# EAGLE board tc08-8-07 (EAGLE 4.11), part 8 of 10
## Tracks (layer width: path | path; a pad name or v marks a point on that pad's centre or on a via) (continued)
N$155  (via drill 0.61) (continued)
  Route15 0.254: v196.89,121.59 v192.44,126.03 | v211.17,122.22 v214.03,122.22 | v223.24,119.69 223.56,119.69 v230.22,113.02 | v233.4,112.38 v236.26,109.52
  Bottom 0.254: v196.89,121.59 197.2,121.91 210.86,121.91 v211.17,122.22 | v214.03,122.22 214.35,121.91 214.98,121.91 217.52,119.37 222.92,119.37 v223.24,119.69 | v230.22,113.02 230.86,112.38 v233.4,112.38 | v236.26,109.52 236.57,109.84 238.48,109.84 242.92,114.29 C10.L1
N$161  (via drill 0.61)
  Top 0.254: v251.5,257.48 251.18,257.16 251.18,250.81 254.35,247.64 254.35,243.83 255.31,242.87 255.31,238.75 A09.P2
  Bottom 0.254: v251.5,257.48 250.54,258.43 245.15,258.43 244.51,259.07 234.99,259.07 234.03,260.02 A11.F1
N$162  (via drill 0.61)
  Top 0.254: A12.D1 220.38,267.32 220.38,272.4 A12.B1 | v236.26,261.93 236.26,257.8 A11.H1
  Bottom 0.254: v236.26,261.93 232.76,265.42 224.83,265.42 223.87,266.37 221.33,266.37 A12.D1
N$185  (via drill 0.61)
  Top 0.254: v215.62,141.59 215.94,141.91 v215.94,147.94 | v220.06,147.94 221.02,148.89 221.02,150.8 221.97,151.75 221.97,156.52 v221.65,156.83 | v228.32,155.56 228.64,155.24 228.64,140.64 v228.95,140.32
  Route15 0.254: v201.97,141.91 200.38,140.32 200.38,138.74 198.79,137.15 C14.C1 | v228.95,140.32 229.59,140.32 v239.43,130.48
  Bottom 0.254: v201.97,141.91 202.28,141.59 204.19,141.59 204.51,141.27 205.78,141.27 206.09,141.59 v215.62,141.59 | v215.94,147.94 v220.06,147.94 | v221.65,156.83 225.46,156.83 226.73,155.56 v228.32,155.56 | v239.43,130.48 241.34,130.48 242.29,131.43 246.1,131.43 247.05,130.48 248.64,130.48 C10.E1
N$193  (via drill 0.61)
  Top 0.254: v197.2,114.29 196.25,115.24 196.25,119.37 195.62,120 C14.J1
  Route15 0.254: v205.14,106.35 v197.2,114.29 | v217.84,107.3 218.16,107.3 220.38,105.08 221.65,105.08 226.41,100.32 230.22,100.32 v232.45,98.1
  Bottom 0.254: v205.14,106.35 205.46,106.67 217.21,106.67 v217.84,107.3 | v232.45,98.1 234.03,96.51 241.34,96.51 241.97,95.87 242.61,95.87 244.83,98.1 248.64,98.1 C10.S1
PAR  (via drill 0.61)
  Top 0.254: v45.76,247.96 47.34,246.37 47.34,241.29 48.3,240.33 48.3,239.7 47.98,239.38 47.98,234.3 53.69,228.59 53.69,224.78 55.28,224.78 55.92,225.41 55.92,227.95 A25.T1 | v43.22,249.86 41.63,251.45 41.63,254.62 40.99,255.26 40.99,261.61 v42.58,263.19 | v45.12,265.74 44.8,266.05 44.8,282.56 v54.33,292.09 | v291.82,295.9 298.49,295.9 298.49,267.96 298.8,267.64 298.8,262.88 299.12,262.56 299.12,258.11 298.8,257.8 298.8,251.45 298.49,251.13 298.49,249.86 v298.8,249.54
  Route2 0.254: v293.72,247 293.72,246.68 276.58,229.54 276.58,227.64 274.99,226.05 A08.U1
  Bottom 0.254: v45.76,247.96 43.85,249.86 v43.22,249.86 | v45.12,265.74 v42.58,263.19 | v54.33,292.09 54.96,291.45 56.23,291.45 57.19,290.5 62.27,290.5 62.9,289.86 81.95,289.86 83.22,291.13 97.19,291.13 97.83,290.5 130.53,290.5 132.12,292.09 144.18,292.09 144.5,291.77 181.33,291.77 182.6,293.04 202.92,293.04 203.24,292.72 206.41,292.72 206.73,293.04 209.27,293.04 211.17,294.94 230.22,294.94 231.18,293.99 234.67,293.99 235.3,294.63 267.69,294.63 268.96,295.9 v291.82,295.9 | v298.8,249.54 298.17,248.91 295.63,248.91 v293.72,247
PAR\  (via drill 0.61)
  Top 0.254: v223.56,271.45 222.6,270.5 222.6,265.1 223.56,264.15 A12.E1 | v274.36,271.45 273.4,270.5 273.4,236.52 274.67,235.26 A08.S1 | v325.16,179.06 325.16,175.25 B04.M1 | v288.96,205.73 289.28,206.05 289.28,220.33 v288.33,221.29 | v274.36,222.24 273.09,223.51 273.09,228.9 271.5,230.49 v271.18,230.49
  Route15 0.254: v325.16,179.06 324.84,179.06 315.95,187.95 315.31,187.95 312.14,191.12 312.14,192.08 v302.93,201.28
  Bottom 0.254: v223.56,271.45 226.41,274.31 253.72,274.31 254.04,273.99 257.85,273.99 258.16,274.31 266.42,274.31 269.59,271.13 274.04,271.13 v274.36,271.45 | v302.93,201.28 301.03,203.19 298.8,203.19 297.53,204.46 290.23,204.46 v288.96,205.73 | v288.33,221.29 288.01,220.97 275.63,220.97 v274.36,222.24 | v271.18,230.49 272.13,231.45 274.04,231.45 A08.S1
PC+ES  (via drill 0.61)
  Top 0.254: v229.27,268.28 228.95,267.96 228.95,258.75 229.91,257.8 A11.H2
  Route15 0.254: v229.27,268.28 228.32,269.23 224.83,269.23 224.51,269.55 A12.C1
PC+ES\
  Top 0.254: B11.R2 226.73,165.72 225.78,166.68 225.78,203.82 227.05,205.09 227.05,220.33 225.78,221.6 225.78,252.4 226.73,253.35 A11.J2
PWR_CLR\  (via drill 0.61)
  Top 0.254: v222.6,246.05 222.6,255.26 221.97,255.89 221.97,271.13 223.87,273.04 A12.A1 | A10.H2 242.92,253.99 244.19,252.72 244.19,247.64 242.92,246.37 A10.M2 | v230.22,96.83 C11.U2 | v234.03,73.33 234.35,73.65 234.35,87.94 234.67,88.25 234.67,90.79 v233.72,91.74 | v314.36,147.31 314.36,140.96 314.04,140.64 314.04,119.05 313.09,118.1 C05.K1 | v268.32,147.31 B08.U2 | v270.23,90.79 270.23,94.6 269.91,94.92 269.91,95.55 270.23,95.87 270.23,110.8 271.82,112.38 271.82,112.7 272.45,113.33 273.72,113.33 273.72,112.07 273.4,111.75 273.4,108.89 v274.04,108.25 | v81.63,242.87 82.27,242.87 83.54,244.14 A23.M1 | v73.06,241.61 70.2,238.75 70.2,229.22 v70.52,228.9 | v28.61,227.64 28.29,227.32 v28.29,146.36 | v89.57,112.7 89.25,112.38 89.25,69.84 91.79,67.3 v91.79,62.22 | v170.22,59.36 v172.44,57.14 | v189.58,60.63 190.54,61.58 190.54,66.98 193.39,69.84 193.39,72.38 194.03,73.01 194.03,87.3 193.08,88.25 v193.08,89.21 | v194.98,91.74 194.66,92.06 194.66,93.97 193.71,94.92 193.71,97.14 194.98,98.41 194.98,100.95 C14.R1
  Route2 0.254: v193.08,89.21 193.08,89.84 v194.98,91.74
  Route15 0.254: v256.26,90.47 v258.16,92.38
  Bottom 0.254: 222.6,245.73 237.84,245.73 239.11,244.46 A10.M2 | 222.6,245.73 168.95,245.73 168.63,246.05 164.18,246.05 163.87,245.73 105.45,245.73 105.13,246.05 90.21,246.05 89.89,245.73 85.76,245.73 84.81,244.78 A23.M1 | 222.6,245.73 v222.6,246.05 | v230.22,96.83 231.49,96.83 231.49,99.05 230.86,99.68 197.52,99.68 195.93,101.27 C14.R1 | v234.03,73.33 235.94,73.33 D11.A1 | C11.U2 230.86,91.74 v233.72,91.74 234.03,91.43 235.3,91.43 235.94,90.79 246.73,90.79 247.05,91.11 248.32,91.11 248.64,90.79 253.08,90.79 253.4,91.11 254.67,91.11 255.31,90.47 v256.26,90.47 | 307.69,115.56 309.28,117.14 312.14,117.14 C05.K1 | 307.69,115.56 298.17,106.03 295.31,106.03 294.36,105.08 C06.P2 | v268.32,147.31 268.64,146.99 314.04,146.99 v314.36,147.31 | v258.16,92.38 259.12,93.33 262.61,93.33 263.56,92.38 263.56,91.43 267.05,91.43 267.69,90.79 v270.23,90.79 | v274.04,108.25 274.36,108.57 276.58,108.57 283.56,115.56 307.69,115.56 | v81.63,242.87 74.33,242.87 v73.06,241.61 | v70.52,228.9 68.93,227.32 40.68,227.32 40.36,227.64 37.5,227.64 37.18,227.32 28.93,227.32 v28.61,227.64 | v28.29,146.36 28.29,140.96 37.5,140.96 65.76,112.7 v89.57,112.7 | v91.79,62.22 95.6,58.41 145.13,58.41 145.77,59.04 169.9,59.04 v170.22,59.36 | v172.44,57.14 174.34,59.04 188,59.04 v189.58,60.63
RD+WD  (via drill 0.61)
  Top 0.254: v260.7,171.44 260.7,182.87 v261.02,183.18 | v267.37,183.18 267.05,183.5 267.05,194.93 267.37,195.25 267.37,199.06 266.74,199.7 266.74,200.33 267.05,200.65 267.05,204.77 265.78,206.05 265.78,220.97 269.59,224.78 269.59,226.05 268.32,227.32 v268.32,229.86 | v262.29,233.35 262.29,237.48 A09.P1 | v125.77,93.65 123.54,93.65 123.54,182.55 122.91,183.18 122.91,186.04 123.86,186.99 123.86,190.8 v128.62,195.57 | v204.82,195.57 201.01,195.57 200.38,196.2 200.38,201.28 v200.7,201.6 200.38,201.92 200.38,203.82 200.7,204.14 200.7,207.95 205.14,207.95 207.68,210.49 v208.32,210.49 | v220.7,106.03 C12.R1 | v257.85,232.71 256.89,231.76 256.89,222.87 255.94,221.92 255.94,220.97 253.4,218.43 v252.45,218.43 | v223.87,218.43 222.92,218.43 222.29,219.06 217.52,219.06 217.52,217.79 215.94,216.21 v215.94,210.49
  Route2 0.254: v196.25,93.33 v207.36,104.44
  Bottom 0.254: v261.02,183.18 261.34,182.87 267.05,182.87 v267.37,183.18 | v268.32,229.86 265.78,232.4 263.24,232.4 v262.29,233.35 261.97,233.03 258.16,233.03 v257.85,232.71 | v260.7,171.44 B08.N2 | v220.7,106.03 208.95,106.03 v207.36,104.44 | v196.25,93.33 190.54,93.33 189.9,92.7 187.04,92.7 186.41,93.33 165.14,93.33 164.5,92.7 161.64,92.7 161.01,93.33 152.44,93.33 151.8,92.7 148.94,92.7 147.99,93.65 v125.77,93.65 | v128.62,195.57 131.8,198.74 135.61,198.74 138.47,201.6 143.23,201.6 143.55,201.28 166.09,201.28 166.41,201.6 v200.7,201.6 | v204.82,195.57 212.76,195.57 213.71,196.52 B12.D2 | v252.45,218.43 252.13,218.74 224.19,218.74 v223.87,218.43 | v208.32,210.49 v215.94,210.49
RD_EN  (via drill 0.61)
  Top 0.254: v227.37,118.41 225.78,116.83 225.78,109.52 226.73,108.57 C11.N2
  Bottom 0.254: v227.37,118.41 229.27,120.32 232.76,120.32 C11.J1
RD_EN_LPB_00-02  (via drill 0.61)
  Top 0.254: 257.53,53.64 257.53,60.31 258.8,61.58 D09.D1 | 257.53,53.64 257.53,47.61 | 257.53,47.61 257.53,33.32 258.48,32.37 D09.R1 | 257.53,47.61 v259.12,47.61 | v203.24,134.29 202.92,133.97 202.92,96.83 201.97,95.87 C13.T2 | v257.85,53.64 257.53,53.64 | v219.11,50.47 218.79,50.79 218.79,62.22 v216.89,64.12 | v196.89,62.85 196.57,63.17 196.57,71.43 196.25,71.74 196.25,87.94 196.57,88.25 196.57,91.74 v196.25,92.06
  Route15 0.254: v196.25,92.06 v199.11,94.92
  Bottom 0.254: v259.12,47.61 D09.K1 | v203.24,134.29 203.55,134.61 209.59,134.61 210.22,133.97 213.08,133.97 213.71,134.61 222.29,134.61 222.92,133.97 225.78,133.97 226.41,134.61 234.99,134.61 235.94,133.65 239.11,133.65 C10.D2 | v257.85,53.64 256.89,52.69 244.83,52.69 241.65,49.52 220.06,49.52 v219.11,50.47 | v216.89,64.12 214.98,62.22 197.52,62.22 v196.89,62.85 | v199.11,94.92 201.01,94.92 C13.T2
RD_EN_LPB_03-05  (via drill 0.61)
  Top 0.254: D09.U2 255.31,22.85 254.35,23.8 254.35,35.86 252.77,37.45 D09.N2 252.77,38.72 254.35,40.31 254.35,52.38 255.31,53.33 D09.H2 | v244.83,55.23 244.83,66.98 v242.29,69.52 | v239.75,72.06 239.75,86.98 241.65,88.89 241.65,96.19 v242.29,96.83
  Route2 0.254: v242.29,96.83 238.8,100.32 239.43,100.95 C10.R2
  Bottom 0.254: C13.R2 202.28,101.91 203.24,102.86 238.16,102.86 239.11,101.91 C10.R2 | v244.83,55.23 254.04,55.23 254.99,54.28 D09.H2 | v242.29,69.52 v239.75,72.06
RDD_00  (via drill 0.61)
  Top 0.254: v261.02,61.9 261.66,62.53 261.66,66.03 D09.C1 | v99.41,218.11 102.59,221.29 102.59,224.46 102.91,224.78 A21.U2 102.91,226.05 101.95,227 101.95,232.4 102.27,232.71 102.27,236.52 98.78,240.02 98.78,249.23 101.32,251.77 101.32,257.16 v101,257.48 | v72.43,211.12 67.03,205.73 67.03,199.7 65.12,197.79 65.12,195.57 63.85,194.3 63.85,173.34 67.35,169.85 v67.66,169.85 | v77.19,166.36 79.09,164.45 79.09,150.48 76.55,147.94 76.55,100.32 76.87,100 76.87,99.36 76.55,99.05 76.55,59.68 v77.51,58.72 | v154.02,56.18 159.1,51.1 v159.1,44.75 | v202.92,39.36 203.24,39.68 v203.24,49.2 | v210.22,50.79 209.9,50.47 209.9,45.71 210.54,45.07 210.54,42.53 209.9,41.9 209.9,38.72 212.76,35.86 216.25,35.86 216.25,33.96 v218.16,32.06 | v207.05,224.78 206.09,225.73 206.09,226.05 203.55,228.59 203.55,252.72 v203.87,253.04 | v201.97,252.4 200.38,252.4 200.38,254.62 201.01,255.26 201.01,259.07 199.74,260.34 199.74,265.42 192.12,273.04 192.12,273.99 188.63,277.48 188.63,282.24 188.95,282.56 188.95,283.83 176.88,295.9 v172.44,295.9 | v100.68,292.72 99.1,291.13 99.1,273.99 98.46,273.36 98.46,272.72 101,270.18 101,267.64 101.32,267.32 101.32,265.1 100.37,264.15 v100.37,263.19
  Route2 0.254: v218.16,32.06 219.11,32.06 220.06,33.01 224.83,33.01 227.68,35.86 229.27,35.86 239.75,46.34 239.75,46.98 v249.59,56.82 | v100.37,263.19 103.54,260.02 v101,257.48
  Route15 0.254: v207.05,224.78 208.32,223.51 208.95,224.14 209.9,224.14 214.67,219.38 224.19,219.38 225.78,217.79 225.78,217.48 228.32,214.93 230.22,214.93 238.48,206.68 239.11,206.68 251.18,194.61 251.18,189.85 254.35,186.68 254.35,180.33 255.31,179.37 255.31,175.25 B09.M2
  Bottom 0.254: v261.02,61.9 257.53,58.41 254.04,58.41 253.08,57.46 D09.F2 251.81,56.82 v249.59,56.82 | v99.41,218.11 92.43,211.12 v72.43,211.12 | v67.66,169.85 71.16,166.36 v77.19,166.36 | v77.51,58.72 80.36,55.87 132.43,55.87 133.07,56.5 134.66,56.5 135.29,55.87 153.71,55.87 v154.02,56.18 | v159.1,44.75 160.37,43.49 162.28,43.49 165.77,39.99 189.58,39.99 190.22,39.36 v202.92,39.36 | v203.24,49.2 206.09,52.06 208.95,52.06 v210.22,50.79 | v203.87,253.04 203.55,252.72 202.28,252.72 v201.97,252.4 | v172.44,295.9 172.12,296.22 145.77,296.22 144.82,295.26 135.29,295.26 134.66,295.9 133.39,295.9 131.48,293.99 131.16,293.99 129.58,292.41 101,292.41 v100.68,292.72
RDD_01  (via drill 0.61)
  Top 0.254: v255.62,45.39 D09.M2 255.31,40.63 254.99,40.31 v254.99,37.77 | v199.43,150.8 199.74,151.12 199.74,168.26 v200.06,168.58 | v201.01,41.58 200.38,40.95 200.38,28.88 199.74,28.25 199.74,20.31 187.68,8.24 101.64,8.24 101.64,74.28 v99.1,76.82 | v94.02,81.9 93.06,82.86 93.06,87.62 92.43,88.25 92.43,145.72 v94.02,147.31
  Route15 0.254: v240.07,33.32 236.89,36.5 231.81,36.5 225.78,42.53 215.62,42.53 v211.49,38.4
  Bottom 0.254: v255.62,45.39 258.48,48.25 258.48,50.15 D09.J1 | 124.81,149.21 120.37,153.66 118.15,153.66 116.56,155.24 B20.U2 | 124.81,149.21 137.83,149.21 138.15,148.89 146.4,148.89 147.04,148.26 178.47,148.26 180.38,150.17 185.14,150.17 185.77,149.53 188,149.53 188.31,149.85 198.47,149.85 v199.43,150.8 | v200.06,168.58 201.01,169.53 260.39,169.53 261.34,168.58 B09.P1 | v254.99,37.77 253.4,36.18 253.4,35.23 250.86,35.23 249.91,36.18 248,36.18 245.46,33.64 240.38,33.64 v240.07,33.32 | v211.49,38.4 211.17,38.72 209.27,38.72 208,39.99 203.87,39.99 202.28,41.58 v201.01,41.58 | v99.1,76.82 v94.02,81.9 | v94.02,147.31 94.33,147.62 113.07,147.62 114.65,149.21 124.81,149.21
RDD_02  (via drill 0.61)
  Top 0.254: v259.12,28.25 261.66,30.78 261.66,34.28 D09.P1 | v104.81,222.55 105.13,222.24 105.13,220.02 v107.03,218.11 | v110.53,214.62 111.16,213.98 v111.16,206.68 | v106.72,205.73 104.81,203.82 v104.81,193.34 | v87.67,188.58 86.08,186.99 86.08,170.17 v86.4,169.85 | v84.49,169.85 82.9,169.85 82.9,71.74 v84.49,70.16 | v137.83,59.36 139.42,57.77 139.42,33.64 145.13,27.93 145.13,27.29 146.09,26.34 148.31,26.34 148.31,26.66 148.94,27.29 152.75,27.29 152.75,20.94 153.07,20.62 153.07,18.72 157.2,14.59 190.85,14.59 190.85,24.75 196.57,30.47 196.57,31.42 v197.2,32.06 | v201.01,28.25 206.41,22.85 207.68,22.85 207.68,20.62 206.41,19.35 v206.41,18.72 | v239.43,13.01 245.46,13.01 245.46,12.69 246.42,11.74 253.72,11.74 253.72,19.67 252.77,20.62 252.77,24.75 D09.T2 | v190.54,152.39 190.22,152.07 190.22,146.67 187.68,144.13 187.68,134.29 v187.36,133.97 | v144.18,92.7 143.23,91.74 143.23,87.62 143.55,87.3 143.55,77.77 141.01,75.24 v141.01,74.92 | v120.05,72.06 117.51,72.06 v117.51,70.16
  Route2 0.254: v197.2,32.06 v201.01,28.25 | v249.27,191.76 249.27,191.44 237.21,179.37 237.21,179.06 229.59,171.44 229.59,170.49 228.95,169.85 227.37,169.85 218.16,160.64 214.35,160.64 v208.63,154.93 | v187.36,133.97 186.09,133.97 172.12,120 171.17,120 157.83,106.67 154.02,106.67 146.4,99.05 146.4,94.92 v144.18,92.7
  Route15 0.254: v206.41,18.72 207.36,17.77 208.32,17.77 209.59,16.5 211.49,16.5 212.13,15.86 217.52,15.86 218.16,15.23 218.79,15.23 221.97,12.05 236.57,12.05 238.48,13.96 v239.43,13.01
  Bottom 0.254: v259.12,28.25 257.53,26.66 254.04,26.66 253.08,25.71 D09.T2 | v104.81,222.55 106.4,224.14 114.34,224.14 115.29,225.09 A20.U2 | v110.53,214.62 v107.03,218.11 | v111.16,206.68 111.16,205.09 108.3,205.09 107.67,205.73 v106.72,205.73 | v104.81,193.34 100.05,188.58 v87.67,188.58 | v86.4,169.85 v84.49,169.85 | v84.49,70.16 86.08,68.57 114.97,68.57 115.61,69.2 116.24,69.2 | 116.24,69.2 123.86,61.58 135.61,61.58 v137.83,59.36 | v249.27,191.76 250.54,193.03 254.67,193.03 254.99,193.34 B09.E2 | v208.63,154.93 207.36,153.66 197.2,153.66 196.89,153.34 196.25,153.34 195.93,153.66 194.35,153.66 193.71,153.02 191.17,153.02 v190.54,152.39 | v141.01,74.92 137.83,71.74 120.37,71.74 v120.05,72.06 | v117.51,70.16 116.56,69.2 116.24,69.2
RDMK
  Top 0.254: CD18.AS2 141.01,99.05 139.74,100.32 139.74,144.13 141.32,145.72 B18.U2
READ_ALL\  (via drill 0.61)
  Top 0.254: v254.67,96.83 254.35,96.51 254.35,90.79 v256.26,88.89 | v281.34,51.1 281.34,49.83 v283.25,47.93 | v285.15,46.03 285.47,45.71 285.47,39.68 284.52,38.72 D07.N1
  Route2 0.254: v285.15,46.03 v283.25,47.93
  Route15 0.254: v248.96,96.83 240.38,105.4 240.38,106.03 239.75,106.67 239.11,106.67 237.21,108.57 237.21,109.84 236.89,110.16 236.89,110.48 C11.M1 | v261.34,83.81 v256.26,88.89 | v268.64,74.92 269.91,74.92 v280.39,64.44
  Bottom 0.254: v254.67,96.83 v248.96,96.83 | v261.34,83.81 266.1,79.05 266.1,77.77 267.05,77.77 268.64,76.19 v268.64,74.92 | v280.39,64.44 281.02,63.81 282.61,63.81 283.56,64.76 284.83,64.76 286.1,63.49 286.1,52.06 283.25,52.06 282.29,51.1 v281.34,51.1
READ_DATA  (via drill 0.61)
  Top 0.254: v236.26,119.05 235.94,119.37 235.94,122.86 236.26,123.18 C11.H1 | v265.78,73.01 v265.78,84.13 | v280.71,58.72 280.71,55.87 278.17,53.33 278.17,51.42 D07.J2 | v216.89,151.43 216.89,145.4 v217.52,144.77
  Route2 0.254: v273.09,66.35 277.21,62.22 277.21,61.58 280.39,58.41 v280.71,58.72 | v229.91,211.44 238.48,220.02 238.48,229.54 241.02,232.08 241.02,232.71 244.83,236.52 244.83,241.92 245.78,242.87 245.78,247 A10.L1 | v243.24,178.42 241.65,176.83 241.65,174.61 239.75,172.71 238.48,172.71 230.86,165.09 229.59,165.09 228.32,163.82 228.32,161.91 222.29,155.88 221.33,155.88 v216.89,151.43
  Route15 0.254: v234.03,115.88 235.62,115.88 235.94,116.19 236.57,116.19 237.21,115.56 237.21,113.65 243.88,106.99 243.88,106.35 254.35,95.87 255.62,95.87 258.16,93.33 258.48,93.33 260.07,91.74 260.07,91.11 265.78,85.39 v265.78,84.13 | v265.78,73.01 265.78,72.38 266.1,72.06 266.1,71.43 267.37,70.16 268.01,70.16 v268.64,69.52 | v229.91,211.44 229.91,211.12 235.94,205.09 238.16,205.09 238.48,204.77 240.07,204.77 241.02,203.82 241.02,202.24 239.11,200.33 248,191.44 248,190.49 250.54,187.95 250.54,183.18 249.59,182.23 248.32,182.23 246.73,180.64 v246.42,180.96 | v217.52,144.77 221.97,140.32 221.97,138.42 222.6,137.78 224.51,137.78 229.59,132.7 230.22,132.7 230.86,132.07 230.86,131.43 231.49,130.8 231.49,130.16 233.4,128.26 234.03,128.26 234.67,127.62 234.67,126.03 236.26,124.45 C11.H1
  Bottom 0.254: v236.26,119.05 234.99,117.78 234.67,117.78 234.03,117.14 v234.03,115.88 | v268.64,69.52 268.96,69.2 270.23,69.2 v273.09,66.35 | v246.42,180.96 243.88,178.42 v243.24,178.42
READ_DATA\  (via drill 0.61)
  Top 0.254: v283.25,130.48 282.93,130.16 282.93,106.35 282.29,105.72 282.29,95.24 282.93,94.6 282.93,52.38 283.88,51.42 D07.J1 | v245.78,134.93 244.83,135.88 244.83,158.1 244.51,158.42 244.51,159.05 247.37,161.91 247.37,166.99 v247.05,167.31 | v266.1,167.95 266.1,170.49 266.42,170.8 266.42,176.2 265.47,177.15 B08.L2 | v228.64,190.17 227.68,189.22 227.68,185.09 227.37,184.77 B11.J2 | v243.24,191.76 244.83,190.17 244.83,177.15 v245.78,176.2
  Bottom 0.254: v283.25,130.48 282.29,131.43 270.86,131.43 270.23,132.07 264.51,132.07 262.61,133.97 260.07,133.97 259.43,134.61 250.86,134.61 250.23,133.97 247.37,133.97 246.42,134.93 v245.78,134.93 | v247.05,167.31 247.37,166.99 265.15,166.99 v266.1,167.95 | v228.64,190.17 230.22,191.76 v243.24,191.76 | v245.78,176.2 246.1,176.52 260.7,176.52 261.97,177.79 B08.L2
RSTA\  (via drill 0.61)
  Top 0.254: v320.39,166.36 320.39,152.39 322.93,149.85 322.93,140.64 322.62,140.32 C04.B1 | 339.44,184.46 339.44,169.85 338.49,168.9 B03.P1 | 339.44,184.46 339.44,194.61 338.17,195.89 B03.C1 | v338.81,184.46 339.44,184.46
  Bottom 0.254: B03.F2 329.28,190.17 330.87,188.58 332.46,188.58 334.68,186.36 334.68,184.77 B03.J1 335.63,184.46 v338.81,184.46 | v320.39,166.36 333.09,166.36 334.36,167.63 | 334.36,167.63 334.68,167.95 337.54,167.95 B03.P1 | 334.36,167.63 332.46,169.53 332.14,169.53 332.14,173.98 B03.M2
RSTB\  (via drill 0.61)
  Top 0.254: B04.M2 319.76,174.93 320.39,175.56 320.39,179.06 321.98,180.64 321.98,183.5 B04.J1 | B04.J1 322.62,184.77 323.57,185.73 323.57,191.76 v323.25,192.08 324.2,193.03 324.2,198.43 325.16,199.38 B04.C1 | v323.57,131.43 323.57,151.75 323.89,152.07 323.89,160.96 324.2,161.28 324.2,166.68 | 324.2,166.68 325.16,167.63 B04.P1 | 324.2,166.68 324.2,182.55 322.93,183.82 B04.J1
  Bottom 0.254: v323.25,192.08 322.93,191.76 317.54,191.76 316.58,190.8 B04.F2 | v323.57,131.43 317.22,131.43 316.58,132.07 311.19,132.07 310.23,133.02 C05.D1
SE\  (via drill 0.61)
  Top 0.254: v258.48,223.83 259.12,223.83 260.07,222.87 260.07,218.74 v259.75,218.43 | v221.02,111.43 221.97,110.48 221.97,104.13 v221.65,103.81
  Route2 0.254: v274.67,241.29 270.23,245.73 268.32,245.73 267.69,246.37 267.69,247 265.78,248.91 264.83,248.91 263.88,249.86 263.88,250.81 265.15,252.08 262.29,254.94 262.29,256.53 A09.H1 | v262.29,210.17 262.29,208.58 260.7,207 260.7,202.87 255.62,197.79 255.62,196.2 251.81,192.39 251.81,191.76 248,187.95 248,183.18 248.64,182.55 248,181.92 248,162.55 238.48,153.02 238.48,147.94 237.84,147.31 237.84,146.04 235.3,143.5 235.3,133.34 224.51,122.54 224.51,121.91 223.24,120.64 222.92,120.64 222.29,120 222.29,119.05 221.02,117.78 221.02,115.88 223.24,113.65 v221.02,111.43 | v243.88,77.77 248,73.65 248.64,74.28 251.18,74.28 v259.12,66.35
  Route15 0.254: v274.67,241.29 272.45,239.06 272.45,238.11 262.29,227.95 261.34,227.95 257.85,224.46 v258.48,223.83 | v221.65,103.81 221.97,103.81 226.1,99.68 227.05,99.68 228,98.73 228,97.14 232.76,92.38 232.76,91.43 234.67,89.52 234.67,88.89 243.88,79.68 v243.88,77.77 | v259.12,66.35 v280.71,44.75
  Bottom 0.254: v259.75,218.43 259.75,216.52 262.29,213.98 v262.29,210.17 | v280.71,44.75 283.56,44.75 D07.L1
SEARCH  (via drill 0.61)
  Top 0.254: v190.85,45.71 190.22,46.34 190.22,58.72 186.41,62.53 186.41,65.39 187.04,66.03 187.04,69.52 184.5,72.06 184.5,78.09 v186.09,79.68 | v191.17,80.95 191.49,81.27 191.49,89.52 193.39,91.43 193.39,93.33 192.12,94.6 v192.12,95.87 | v214.03,112.7 214.98,112.7 214.98,113.02 215.62,113.65 215.62,114.92 214.35,116.19 214.35,118.73 215.62,120 215.62,121.27 214.98,121.91 214.98,123.49 v214.67,123.81
  Route2 0.254: v192.12,95.87 192.44,95.87 197.84,101.27 198.79,101.27 204.82,107.3 205.46,107.3 v207.68,109.52 | v214.67,123.81 v223.56,132.7
  Route15 0.254: v258.48,46.34 253.08,46.34 v252.77,46.66 | v238.8,46.66 237.21,45.07 v236.89,45.07
  Bottom 0.254: v258.48,46.34 269.59,46.34 269.59,53.33 272.77,56.5 273.72,56.5 277.21,60 280.39,60 D07.E2 | v252.77,46.66 251.81,45.71 244.83,45.71 244.19,45.07 241.02,45.07 239.43,46.66 v238.8,46.66 | v236.89,45.07 234.99,43.17 193.39,43.17 v190.85,45.71 | v186.09,79.68 187.36,80.95 v191.17,80.95 | v207.68,109.52 210.54,112.38 213.71,112.38 v214.03,112.7 | v223.56,132.7 223.87,133.02 226.41,133.02 C11.D2
SEARCH\  (via drill 0.61)
  Top 0.254: v258.16,175.56 257.53,176.2 257.53,178.42 v259.12,180.01 | v287.06,69.2 287.69,69.84 287.69,71.43 289.28,73.01 289.28,81.9 v288.01,83.17 | v280.71,82.86 v280.71,88.57 | D07.E1 v287.37,63.17
  Route2 0.254: v287.37,63.17 287.37,64.76 285.15,66.98 287.06,68.88 v287.06,69.2 | v290.87,91.11 291.82,92.06 291.82,93.02 v293.09,94.28
  Route15 0.254: v236.26,179.37 238.48,179.37 239.75,180.64 245.15,175.25 246.73,175.25 v248.96,173.02 249.91,172.07 249.91,171.76 263.24,158.42 263.24,151.43 263.88,150.8 263.88,147.94 266.74,145.08 266.74,136.2 267.05,135.88 267.05,129.53 268.96,127.62 268.96,126.03 271.18,123.81 270.23,122.86 270.23,120 276.9,113.33 276.9,112.07 280.39,108.57 280.71,108.57 286.42,102.86 286.42,101.27 293.09,94.6 v293.09,94.28
  Bottom 0.254: v236.26,179.37 232.13,179.37 230.86,180.64 B11.K2 | v248.96,173.02 249.27,173.34 251.18,173.34 253.72,175.88 257.85,175.88 v258.16,175.56 | v259.12,180.01 261.34,182.23 301.03,182.23 301.66,181.6 306.11,181.6 B05.K2 | v288.01,83.17 287.69,82.86 v280.71,82.86 | v280.71,88.57 282.93,90.79 282.93,92.06 285.47,92.06 286.74,90.79 290.55,90.79 v290.87,91.11
SEL  (via drill 0.61)
  Top 0.254: v101.64,221.92 101.32,222.24 v101.32,236.21 | v268.64,278.12 263.88,278.12 263.88,264.78 v263.56,264.47
  Route2 0.254: v101.64,221.92 v97.51,217.79 | v163.87,238.43 163.87,239.7 183.87,259.7 183.87,263.19 v184.19,263.51 | v223.87,265.1 223.87,265.42 241.97,283.51 242.29,283.51 v243.88,285.1
  Route15 0.254: v66.71,228.59 66.71,228.27 68.3,226.68 68.62,226.68 70.2,225.09 70.2,224.78 70.84,224.14 71.47,224.14 73.38,222.24 73.38,221.6 v77.51,217.48 | v261.34,286.05 261.34,285.42 v268.64,278.12
  Bottom 0.254: v66.71,228.59 64.81,230.49 60.36,230.49 59.41,231.45 A25.S1 | v77.51,217.48 77.82,217.79 v97.51,217.79 | v101.32,236.21 101.95,236.84 127.99,236.84 131.16,233.67 147.67,233.67 150.21,236.21 155.61,236.21 156.25,236.84 162.28,236.84 v163.87,238.43 | v184.19,263.51 184.19,264.78 223.56,264.78 v223.87,265.1 | v243.88,285.1 244.19,285.42 248.32,285.42 248.96,286.05 259.43,286.05 259.75,285.74 261.02,285.74 v261.34,286.05 | v263.56,264.47 263.56,259.38 265.78,257.16 A08.H2
SEL\  (via drill 0.61)
  Top 0.254: v297.85,186.04 298.17,186.36 298.17,210.81 296.9,212.08 v296.9,220.65 | v254.04,220.33 253.72,220.65 253.72,239.7 252.77,240.65 A09.N2
  Bottom 0.254: v297.85,186.04 323.89,186.04 324.84,186.99 B04.H1 | v296.9,220.65 296.58,220.33 262.29,220.33 261.97,220.02 254.35,220.02 v254.04,220.33 | A08.J2 261.97,253.99 252.77,244.78 252.77,241.92 A09.N2
SH_DTB  (via drill 0.61)
  Top 0.254: 250.54,197.15 249.91,196.52 249.91,194.61 249.59,194.3 B10.E1 249.59,193.03 251.18,191.44 251.18,179.37 252.13,178.42 B09.L2 252.13,177.15 251.18,176.2 251.18,156.52 254.04,153.66 | 250.54,197.15 251.81,197.15 B09.D2 | 250.54,197.15 250.54,200.65 250.23,200.96 250.23,202.24 247.37,205.09 247.37,207.31 247.69,207.63 247.69,218.11 247.37,218.43 247.37,225.41 244.51,228.27 244.51,234.62 240.38,234.62 A10.R2 | B09.B1 259.12,202.55 260.07,201.6 260.07,188.58 261.34,187.31 B09.H1 261.66,186.68 260.07,185.09 260.07,173.02 259.12,172.07 B09.N1 259.12,170.8 260.39,169.53 260.39,163.82 260.7,163.5 260.7,160.96 263.24,158.42 263.24,137.78 | 255.94,101.27 255.94,101.91 258.48,104.44 258.48,107.3 C09.N1 259.12,108.57 260.07,109.52 260.07,133.97 259.43,134.61 259.43,138.74 259.12,139.05 C09.B1 | 255.94,101.27 255.94,99.05 C09.S2 | 255.94,101.27 254.35,102.86 254.35,107.94 253.08,109.21 253.08,113.33 252.77,113.65 C09.L2 252.13,114.92 251.18,115.88 251.18,127.62 252.45,128.89 C09.D2 252.77,133.97 252.77,137.15 254.04,138.42 254.04,153.66 | 254.04,153.66 254.04,155.88 254.67,156.52 254.67,160.64 255.31,161.28 B09.S2 | 263.24,137.78 263.24,128.89 261.97,127.62 C09.H1 | v261.66,139.37 263.24,137.78
  Bottom 0.254: v261.66,139.37 259.43,139.37 C09.B1
SH_EN  (via drill 0.61)
  Top 0.254: v218.79,242.56 218.79,259.07 217.52,260.34 A12.E2 | 248,124.77 246.42,126.35 C10.F1 | 248,124.77 248,112.7 248.96,111.75 C10.M1 | 248,124.77 248,137.15 248.64,137.78 248.64,141.91 248.96,142.23 C10.A1 | v205.14,259.38 202.92,257.16 202.92,219.7 v201.65,218.43 | v180.38,217.16 180.38,207.31 181.01,206.68 181.01,204.46 180.38,203.82 v180.38,202.55
  Route15 0.254: v180.38,202.55 180.38,202.24 190.22,192.39 190.22,191.12 197.84,183.5 197.84,183.18 198.47,182.55 199.74,182.55 205.78,176.52 205.78,175.88 v217.52,164.14 | v224.19,164.45 227.37,167.63 243.88,151.12 244.19,151.12 245.46,149.85 246.1,149.85 247.37,148.58 247.37,145.08 248.96,143.5 C10.A1
  Bottom 0.254: v218.79,242.56 223.24,242.56 223.87,241.92 226.1,241.92 226.41,241.61 A11.N2 | v205.14,259.38 205.46,259.07 208.63,259.07 211.17,261.61 215.3,261.61 216.89,263.19 A12.E2 | v201.65,218.43 200.38,217.16 v180.38,217.16 | v217.52,164.14 219.75,164.14 220.06,163.82 223.56,163.82 v224.19,164.45
SH_EN\  (via drill 0.61)
  Top 0.254: 250.54,120.32 250.54,134.93 249.59,135.88 C10.C1 249.59,137.15 v249.59,139.37 | 250.54,120.32 250.54,106.35 249.59,105.4 C10.P1 | 250.54,120.32 v250.23,120.32 | A11.M2 229.91,243.83 228.95,242.87 228.95,226.36 v228.32,225.73 228.64,225.41 228.64,225.09 230.86,222.87 230.86,209.54 v228,206.68 | v253.08,144.13 251.5,145.72 v251.5,150.8 | v224.19,178.11 222.6,179.69 222.6,182.23 v222.92,182.55 | v219.11,190.8 v219.11,196.52
  Route2 0.254: v249.59,139.37 249.59,140.64 v253.08,144.13 | v218.16,185.73 218.16,186.04 218.79,186.68 218.79,188.58 217.84,189.54 v219.11,190.8 | v219.11,196.52 219.11,197.15 222.92,200.96 222.92,201.6 v228,206.68
  Route15 0.254: v246.1,154.29 237.21,163.18 236.57,163.18 234.99,164.77 234.99,165.4 230.54,169.85 230.22,169.85 229.59,170.49 229.59,172.71 v224.19,178.11
  Bottom 0.254: v250.23,120.32 246.73,120.32 C10.J1 | v228.32,225.73 227.37,225.73 225.14,223.51 215.94,223.51 214.98,222.55 A12.V2 | v251.5,150.8 249.59,152.71 247.69,152.71 v246.1,154.29 | v222.92,182.55 222.92,184.77 221.97,184.77 221.02,185.73 v218.16,185.73
SH_ST  (via drill 0.61)
  Top 0.254: v154.98,140.64 152.44,138.1 152.44,134.29 152.12,133.97 152.12,120 149.58,117.46 149.58,113.33 147.99,111.75 CD18.AM1
  Bottom 0.254: v154.98,140.64 157.2,142.86 C17.A1
SH_ST-B  (via drill 0.61)
  Top 0.254: v160.06,70.16 161.64,71.74 161.64,96.51 166.09,100.95 166.09,104.44 C16.P2
  Bottom 0.254: v160.06,70.16 158.47,68.57 154.02,68.57 152.75,67.3 148.63,67.3 148.31,66.98 CD18.BC1
SHIFT_CK  (via drill 0.61)
  Top 0.254: v132.12,103.81 130.53,102.22 130.53,88.25 130.85,87.94 130.85,76.5 130.53,76.19 130.53,55.55 133.07,53.01 133.07,41.26 136.24,38.09 136.24,33.96 137.83,32.37 CD18.BR2 | v162.6,104.13 162.28,104.44 162.28,115.24 160.69,116.83 C17.K1
  Bottom 0.254: v132.12,103.81 132.43,103.49 161.96,103.49 v162.6,104.13
SINGLE_UNIT  (via drill 0.61)
  Top 0.254: v114.97,159.05 114.65,159.37 114.65,163.18 v116.24,164.77 | v144.82,167.63 145.13,167.95 145.13,170.17 146.4,171.44 146.4,189.22 v147.99,190.8 | v198.16,221.92 v198.16,216.21 | v252.13,233.35 251.18,234.3 251.18,236.52 v252.77,238.11 | v261.97,247.64 A09.K1
  Route2 0.254: v137.83,167.31 140.05,167.31 142.28,165.09 v144.82,167.63 | v164.82,207.63 v147.99,190.8 | v204.82,228.59 v198.16,221.92 | v217.84,221.92 218.48,221.92 220.38,223.83 220.7,223.83 222.6,225.73 222.6,226.05 229.59,233.03 234.67,233.03 v236.89,235.26 | v252.77,238.11 261.97,247.32 v261.97,247.64
  Route15 0.254: v118.78,167.31 v116.24,164.77 | v170.53,208.58 175.61,208.58 v179.42,212.39 | v211.49,227.95 211.81,227.95 v217.84,221.92 | v236.89,235.26 238.8,237.16 239.43,236.52 242.61,236.52 245.46,233.67 v249.27,233.67
  Bottom 0.254: v114.97,159.05 113.38,157.47 105.45,157.47 103.86,155.88 B21.U2 | v118.78,167.31 119.1,166.99 137.51,166.99 v137.83,167.31 | v164.82,207.63 165.77,208.58 v170.53,208.58 | v179.42,212.39 181.01,213.98 195.93,213.98 v198.16,216.21 | v204.82,228.59 206.09,227.32 208.63,227.32 209.27,227.95 v211.49,227.95 | v249.27,233.67 249.59,233.35 v252.13,233.35
SKP_RQ\  (via drill 0.61)
  Route15 0.254: v228,232.71 229.27,232.71 229.59,233.03 244.19,233.03 244.83,232.4 245.78,232.4 256.26,221.92 256.26,221.6 258.16,219.7 261.66,219.7 262.93,218.43 269.28,218.43 271.82,220.97 281.98,220.97 285.47,217.48 286.1,217.48 293.09,210.49 293.09,208.9 298.17,203.82 298.17,198.11 300.71,195.57 300.71,194.93 305.15,190.49 v305.15,190.17
  Bottom 0.254: v228,232.71 225.14,232.71 224.51,232.08 A12.S1 | v305.15,190.17 308.96,190.17 B05.F1
SP_DY\  (via drill 0.61)
  Top 0.254: v186.09,107.62 184.5,106.03 184.5,104.13 184.82,103.81 184.82,102.86 183.87,101.91 183.87,98.41 181.01,95.55 181.01,94.92 183.87,92.06 183.87,88.25 183.55,87.94 183.55,85.71 183.87,85.39 183.87,70.47 184.5,69.84 184.5,63.49 187.04,60.95 187.04,59.36 188.63,57.77 D14.F2
  Route15 0.254: v186.09,107.62 v189.27,110.8
  Bottom 0.254: v189.27,110.8 191.49,110.8 C14.M2
ST_BLK_MK  (via drill 0.61)
  Top 0.254: v137.83,74.92 139.42,76.5 139.42,99.68 138.47,100.63 138.47,100.95 CD18.AR2 138.47,102.22 138.47,105.72 v138.78,106.03
  Route2 0.254: v201.33,130.16 200.38,130.16 199.11,128.89 194.03,128.89 v185.46,120.32
  Route15 0.254: v180.06,120.32 179.42,119.69 179.42,119.37 v171.49,111.43
  Bottom 0.254: v137.83,74.92 137.51,75.24 12.74,75.24 12.42,74.92 4.16,74.92 4.16,236.21 16.86,248.91 40.99,248.91 42.9,250.81 A26.K1 | v185.46,120.32 184.5,119.37 181.96,119.37 181.01,120.32 v180.06,120.32 | v171.49,111.43 171.49,107.3 171.17,107.3 170.53,106.67 146.72,106.67 146.09,106.03 v138.78,106.03 | v201.33,130.16 C13.E2
ST_BLK_MK\  (via drill 0.61)
  Top 0.254: v199.43,127.3 199.74,127.62 199.74,149.21 v198.16,150.8 | v186.09,150.48 184.5,152.07 184.5,157.79 184.82,158.1 184.82,160.96 184.5,161.28 184.5,209.22 v184.19,209.54 | v249.59,210.17 250.23,210.81 250.23,219.7 249.91,220.02 249.91,224.14 250.54,224.78 250.54,239.38 | 250.54,239.38 250.54,261.29 252.13,262.88 252.13,266.05 A09.D2 | v261.34,241.61 261.34,243.51 261.66,243.83 A09.M1 | 250.54,239.38 v251.18,239.38
  Bottom 0.254: v199.43,127.3 201.01,127.3 C13.F2 | v198.16,150.8 197.84,150.48 v186.09,150.48 | v184.19,209.54 184.5,209.22 226.41,209.22 227.68,210.49 228.32,210.49 228.95,209.86 249.27,209.86 v249.59,210.17 | v261.34,241.61 259.75,240.02 258.16,240.02 257.53,240.65 254.99,240.65 253.72,239.38 v251.18,239.38
ST_CK  (via drill 0.61)
  Top 0.254: D17.M2 153.71,40.63 153.71,35.55 D17.P2 | v180.69,83.49 181.01,83.17 181.01,72.38 v179.11,70.47 | v172.44,69.52 171.17,68.25 171.17,61.58 168.95,59.36 168.95,58.09 168.63,57.77 168.63,33.64 v168.95,33.32 | v43.22,52.69 40.99,54.92 40.99,146.36 38.45,148.89 38.45,195.57 v38.77,195.89 | v13.37,217.48 15.59,219.7 v15.59,236.21
  Route2 0.254: v180.69,83.49 184.5,87.3 184.5,92.7 201.01,109.21 201.01,111.75 207.68,118.41 207.68,120 C13.J1
  Bottom 0.254: CD18.BR1 145.13,32.06 146.09,33.01 149.26,33.01 150.85,34.6 153.39,34.6 D17.P2 | D17.P2 154.02,35.55 152.44,37.14 152.12,37.14 151.48,37.77 D17.N2 150.21,37.77 149.26,36.82 59.09,36.82 v43.22,52.69 | v179.11,70.47 177.2,68.57 174.66,68.57 173.71,69.52 v172.44,69.52 | v168.95,33.32 168.63,33.01 158.79,33.01 157.52,34.28 154.34,34.28 D17.P2 | A10.P1 248.64,238.43 247.69,239.38 200.7,239.38 200.38,239.7 190.22,239.7 189.9,239.38 86.4,239.38 86.08,239.7 83.86,239.7 83.54,239.38 51.79,239.38 51.47,239.06 47.34,239.06 46.71,238.43 A26.P1 45.44,237.8 44.17,237.8 42.58,236.21 v15.59,236.21 | v38.77,195.89 38.77,199.06 31.15,206.68 31.15,207.95 17.18,207.95 12.74,212.39 12.74,217.48 v13.37,217.48
ST_CK\  (via drill 0.61)
  Top 0.254: v167.68,120.96 167.99,121.27 167.99,128.58 167.04,129.53 C16.E2
  Bottom 0.254: v167.68,120.96 178.79,109.84 181.33,109.84 184.5,113.02 202.6,113.02 205.14,115.56 208.63,115.56 210.22,117.14 210.54,117.14 C13.K1
ST_CK_0P  (via drill 0.61)
  Top 0.254: v217.21,84.76 217.21,85.39 219.11,85.39 221.97,88.25 221.97,93.33 223.56,94.92 223.56,97.78 C12.S1 | v159.1,76.19 159.1,94.28 161.01,96.19 161.01,96.83 164.82,100.63 164.82,135.56 164.5,135.88 164.5,138.74 165.14,139.37 v165.14,151.12 | v189.9,155.24 191.81,153.34 v191.81,146.36 | v204.51,145.72 207.68,142.55 207.68,140.32 C13.B1 | v223.24,185.73 222.6,186.36 222.6,190.8 v223.24,191.44 | v177.84,188.9 177.52,188.58 v177.52,153.98
  Bottom 0.254: v217.21,84.76 208.63,76.19 199.74,76.19 199.43,75.87 159.42,75.87 v159.1,76.19 | v165.14,151.12 167.68,153.66 177.52,153.66 | 177.52,153.66 187.04,153.66 188.63,155.24 v189.9,155.24 | v191.81,146.36 192.44,145.72 v204.51,145.72 | v223.24,185.73 222.6,186.36 218.79,186.36 218.16,186.99 B12.H2 | v223.24,191.44 222.92,191.76 204.82,191.76 202.28,189.22 194.03,189.22 193.39,188.58 178.15,188.58 v177.84,188.9 | 177.52,153.66 v177.52,153.98
ST_CK_0P\  (via drill 0.61)
  Top 0.254: v149.9,72.06 149.58,71.74 149.58,62.85 152.12,60.31 152.12,46.03 151.17,45.07 D17.L2 | v144.18,72.69 144.5,73.01 144.5,75.24 147.36,78.09 v147.36,90.16 | v155.29,89.84 157.52,92.06 v157.52,92.38 | v164.18,97.78 v167.04,100.63 | v210.86,139.37 210.86,142.23 C13.A1
  Route2 0.254: v157.52,92.38 162.91,97.78 v164.18,97.78 | v176.57,105.08 192.44,120.96 193.71,120.96 197.84,125.08 198.47,125.08 200.38,126.99 200.38,127.94 202.28,129.84 202.28,130.8 v210.86,139.37
  Bottom 0.254: v149.9,72.06 149.58,71.74 145.13,71.74 v144.18,72.69 | v147.36,90.16 154.98,90.16 v155.29,89.84 | v167.04,100.63 167.36,100.32 170.53,100.32 175.3,105.08 v176.57,105.08
ST_DATA  (via drill 0.61)
  Top 0.254: v191.81,121.91 192.76,120.96 v192.76,120 | v181.65,211.44 181.33,211.12 v181.33,209.54 | v173.71,210.49 171.17,207.95 171.17,194.93 167.99,191.76 v167.99,165.4 | v147.99,164.14 146.4,162.55 146.4,159.37 v146.72,159.05 | v128.94,157.79 126.72,155.56 126.72,138.74 v125.45,137.46 | v163.55,123.18 C16.J2
  Route15 0.254: v215.94,205.41 215.3,206.05 218.48,209.22 220.38,209.22 222.92,206.68 223.24,206.68 B12.A1 | v199.11,210.81 v202.92,207
  Bottom 0.254: v191.81,121.91 165.14,121.91 164.18,120.96 C16.J2 | v192.76,120 195.3,122.54 203.24,122.54 204.19,123.49 C13.H2 | v215.94,205.41 215.62,205.09 205.46,205.09 205.14,204.77 204.51,204.77 202.92,206.36 v202.92,207 | v199.11,210.81 198.79,210.49 185.46,210.49 184.5,211.44 v181.65,211.44 | v181.33,209.54 180.38,210.49 v173.71,210.49 | v167.99,165.4 166.41,163.82 148.31,163.82 v147.99,164.14 | v146.72,159.05 145.13,157.47 129.26,157.47 v128.94,157.79 | v125.45,137.46 125.13,137.78 119.1,137.78 116.56,135.24 116.56,131.43 125.45,131.43 131.8,125.08 144.5,125.08 147.04,122.54 162.91,122.54 v163.55,123.18
ST_FINAL  (via drill 0.61)
  Top 0.254: v233.08,117.14 234.67,118.73 234.67,131.43 233.72,132.39 233.72,132.7 C11.D1 | 37.82,239.38 v38.77,240.33 | 37.82,239.38 37.82,227.95 38.14,227.64 38.14,215.25 37.18,214.3 37.18,208.9 37.82,208.27 v37.82,148.26 | v137.2,145.08 136.88,144.77 136.88,71.43 | 136.88,71.43 136.88,46.03 137.83,45.07 CD18.BL2 | v281.66,233.35 282.29,233.99 282.29,269.23 282.93,269.86 v282.93,293.04 | v41.63,289.86 40.99,289.23 40.99,274.94 38.45,272.4 38.45,269.23 38.77,268.91 38.77,264.47 38.45,264.15 38.45,260.34 37.82,259.7 37.82,239.38 | v201.97,110.8 200.38,109.21 200.38,99.05 v200.06,98.73 | v189.27,91.74 187.68,90.16 187.68,78.09 v188,77.77 | v174.66,77.77 174.66,72.06 173.39,70.79 v173.39,68.57 | 136.88,71.43 v138.78,71.43
  Route2 0.254: v201.97,110.8 v204.51,113.33 | v200.06,98.73 198.16,100.63 v189.27,91.74
  Bottom 0.254: v233.08,117.14 228.95,113.02 218.16,113.02 215.62,115.56 213.71,115.56 212.76,114.61 208.63,114.61 C13.L1 207.36,113.97 206.73,113.33 v204.51,113.33 | v38.77,240.33 41.63,240.33 42.26,240.97 A26.N1 | v37.82,148.26 40.68,145.4 57.5,145.4 57.82,145.08 v137.2,145.08 | v281.66,233.35 281.34,233.03 265.15,233.03 263.88,234.3 261.97,234.3 261.34,233.67 257.21,233.67 255.94,232.4 A09.S2 | v282.93,293.04 282.61,293.36 269.28,293.36 268.64,292.72 236.26,292.72 235.62,292.09 220.06,292.09 219.11,293.04 212.13,293.04 210.22,291.13 207.68,291.13 207.05,290.5 191.81,290.5 191.17,291.13 183.55,291.13 182.28,289.86 143.55,289.86 143.23,290.18 133.07,290.18 131.48,288.6 87.98,288.6 87.35,289.23 84.17,289.23 82.9,287.96 61.95,287.96 61.31,288.6 55.28,288.6 54.33,289.55 41.95,289.55 v41.63,289.86 | v174.66,77.77 v188,77.77 | v173.39,68.57 162.91,68.57 160.37,71.11 139.1,71.11 v138.78,71.43
ST_FINAL\  (via drill 0.61)
  Top 0.254: v160.06,126.67 159.1,125.72 159.1,114.29 161.64,111.75 161.64,99.36 v161.96,99.05 | v163.23,96.83 162.28,95.87 162.28,72.38 v163.23,71.43 | v213.4,71.43 213.4,87.94 213.08,88.25 213.08,91.74 v213.71,92.38 | v221.65,97.78 222.6,98.73 222.6,106.67 v222.92,106.99 | v229.91,106.99 229.91,110.48 C11.M2
  Route15 0.254: v213.71,92.38 v217.84,96.51
  Bottom 0.254: C13.M1 211.81,111.43 212.13,111.75 216.25,111.75 216.89,112.38 228.64,112.38 229.59,111.43 C11.M2 | v160.06,126.67 162.91,126.67 C16.F2 | v161.96,99.05 161.96,96.83 v163.23,96.83 | v163.23,71.43 186.41,71.43 186.73,71.74 191.49,71.74 192.12,71.11 205.78,71.11 206.09,70.79 207.05,70.79 207.36,71.11 213.08,71.11 v213.4,71.43 | v217.84,96.51 219.11,97.78 v221.65,97.78 | v222.92,106.99 223.24,106.67 229.59,106.67 v229.91,106.99
ST_IDLE  (via drill 0.61)
  Top 0.254: v33.37,233.35 31.47,233.35 31.47,214.62 31.79,214.3 31.79,207.95 31.47,207.63 31.47,148.89 32.1,148.26 v32.1,100.32 | v134.02,80.63 133.7,80.32 133.7,65.71 v135.29,64.12 | v198.79,113.97 196.25,111.43 v196.25,110.8 | v179.74,89.21 179.11,88.57 179.11,74.6 177.84,73.33 177.84,71.74 178.15,71.43 178.15,67.3 177.84,66.98 v177.84,63.81
  Route2 0.254: v196.25,110.8 194.03,108.57 194.03,104.76 181.65,92.38 181.65,91.11 v179.74,89.21
  Bottom 0.254: v33.37,233.35 36.87,233.35 37.82,234.3 41.95,234.3 42.26,234.62 A26.R1 | v32.1,100.32 32.1,93.97 39.72,93.97 46.07,87.62 127.04,87.62 v134.02,80.63 | v135.29,64.12 135.61,63.81 137.51,63.81 CD18.BD2 138.78,63.17 139.74,62.22 177.84,62.22 v177.84,63.81 | v198.79,113.97 199.43,113.97 201.01,115.56 201.33,115.56 202.6,116.83 203.87,116.83 204.19,117.14 C13.K2
ST_IDLE\  (via drill 0.61)
  Top 0.254: v209.9,119.05 209.9,144.77 211.81,146.67 v211.81,147.31 | v241.97,147.94 242.29,148.26 242.29,154.29 241.65,154.93 241.65,163.82 247.37,169.53 v247.37,182.55 | v261.02,188.9 260.7,189.22 260.7,230.18 260.07,230.81 260.07,239.7 259.12,240.65 A09.N1 258.48,241.92 258.48,244.46 257.21,245.73 257.21,257.48 255.62,259.07 A09.E2
  Bottom 0.254: v209.9,119.05 207.05,116.19 203.87,116.19 202.28,114.61 C13.L2 | v211.81,147.31 212.13,146.99 233.4,146.99 234.35,147.94 v241.97,147.94 | v247.37,182.55 247.37,188.58 260.7,188.58 v261.02,188.9
ST_REV_CK  (via drill 0.61)
  Top 0.254: CD18.BS1 147.99,29.2 148.94,30.15 v148.94,48.88 148.94,53.33 v149.26,53.64 | C11.A1 236.26,143.5 236.26,153.98 235.3,154.93 235.3,156.83 236.26,157.79 236.26,161.28 B11.S1 | v52.74,144.45 47.98,149.21 47.98,207.63 45.76,209.86 45.76,222.24 44.8,223.19 44.8,228.59 41.63,231.76 41.63,246.05 42.58,247 A26.L1 | v206.41,139.05 206.73,139.05 207.68,138.1 207.68,133.97 C13.D1 | v133.39,55.55 133.07,55.87 133.07,86.35 134.02,87.3 134.02,91.11 133.7,91.43 133.7,126.35 v135.29,127.94 | v142.28,128.58 142.59,128.89 142.59,133.02 v142.28,133.34
  Bottom 0.254: v148.94,48.88 148.94,52.06 201.01,52.06 204.82,55.87 212.76,55.87 213.71,56.82 D12.F2 214.98,56.82 217.21,54.6 D12.H2 | v52.74,144.45 130.53,144.45 140.37,134.61 142.28,134.61 | 142.28,134.61 146.09,134.61 146.72,133.97 149.58,133.97 150.21,134.61 158.79,134.61 159.42,133.97 162.28,133.97 162.91,134.61 171.49,134.61 172.12,133.97 174.98,133.97 175.61,134.61 184.19,134.61 186.73,132.07 206.41,132.07 207.36,133.02 C13.D1 | v206.41,139.05 206.73,139.05 207.36,138.42 215.94,138.42 218.79,141.27 230.54,141.27 231.49,142.23 235.62,142.23 235.94,142.55 C11.A1 | v149.26,53.64 149.26,55.23 133.7,55.23 v133.39,55.55 | v135.29,127.94 135.93,128.58 v142.28,128.58 | 142.28,134.61 v142.28,133.34
SWTM  (via drill 0.61)
  Top 0.254: 183.87,107.62 v183.87,103.18 | 183.87,107.62 183.87,108.57 183.23,109.21 183.23,113.33 182.92,113.65 C15.L1 | v293.09,157.15 292.45,157.79 292.45,162.86 293.41,163.82 293.41,167.63 B06.P2 293.41,168.9 293.09,169.21 v293.09,172.07 | A26.V2 v36.55,208.27 | v269.91,174.3 269.59,174.61 269.59,188.58 v268.01,190.17 | v258.48,192.08 256.89,193.66 256.89,195.89 253.4,199.38 v253.4,200.01 | v184.19,107.62 183.87,107.62 | v130.53,112.38 129.89,113.02 129.89,149.53 130.21,149.85 130.21,150.48 129.89,150.8 129.89,173.98 130.53,174.61 130.53,188.9 129.89,189.54 129.89,193.03 130.21,193.34 130.21,195.57 129.89,195.89 v129.89,204.46
  Bottom 0.254: C10.N2 236.57,107.94 234.67,106.03 223.24,106.03 222.29,105.08 218.16,105.08 C12.P2 216.89,104.44 215.94,103.49 202.92,103.49 202.28,102.86 184.19,102.86 v183.87,103.18 | v293.09,157.15 292.14,156.2 290.55,156.2 288.01,153.66 273.09,153.66 272.13,152.71 B08.V1 | v36.55,208.27 62.9,208.27 63.22,208.58 86.4,208.58 90.21,204.77 107.67,204.77 107.99,204.46 112.11,204.46 112.43,204.77 121,204.77 121.32,204.46 v129.89,204.46 137.51,204.46 137.83,204.77 146.4,204.77 146.72,204.46 165.77,204.46 166.09,204.14 168.95,204.14 169.26,204.46 203.87,204.46 204.19,204.14 207.05,204.14 207.36,204.46 228.32,204.46 229.59,203.19 B11.B1 234.03,203.51 234.99,204.46 241.34,204.46 244.51,201.28 252.13,201.28 v253.4,200.01 | v293.09,172.07 292.45,172.71 275.31,172.71 274.67,173.34 274.04,173.34 273.09,174.3 v269.91,174.3 | v268.01,190.17 266.1,192.08 v258.48,192.08 | v184.19,107.62 183.23,106.67 180.69,106.67 178.79,108.57 177.52,108.57 173.71,112.38 v130.53,112.38
SWTM\  (via drill 0.61)
  Top 0.254: v273.09,143.5 273.4,143.81 v273.4,149.85 | v284.52,150.48 285.47,151.43 285.47,156.83 v285.15,157.15
  Route2 0.254: v246.42,119.05 247.37,120 247.37,121.27 248,121.91 248,124.45 v261.66,138.1 | v285.15,157.15 291.18,163.18 291.18,164.14 290.87,164.45 B06.R2
  Bottom 0.254: v246.42,119.05 243.56,116.19 241.97,116.19 240.38,114.61 C10.L2 | v261.66,138.1 261.97,138.42 265.78,138.42 270.86,143.5 v273.09,143.5 | v273.4,149.85 273.72,149.53 283.56,149.53 v284.52,150.48
SYNC  (via drill 0.61)
  Top 0.254: v136.56,148.26 136.24,147.94 136.24,40.31 137.83,38.72 CD18.BN2 | v238.8,146.99 238.48,147.31 238.48,176.2 237.84,176.83 237.84,194.61 239.43,196.2 B10.D2 240.07,196.2 242.29,193.98 B10.E2
  Bottom 0.254: v136.56,148.26 146.09,148.26 146.72,147.62 188.95,147.62 189.27,147.94 205.46,147.94 205.78,148.26 209.59,148.26 211.49,146.36 233.72,146.36 234.35,146.99 v238.8,146.99
SYNC-P\  (via drill 0.61)
  Top 0.254: v204.82,176.2 B13.K2 | v239.75,179.37 B10.J2 | v211.49,203.51 211.49,205.73 B13.A1 | v214.03,200.33 215.62,198.74 215.62,185.73 217.21,184.14 v217.21,182.55
  Bottom 0.254: v204.82,176.2 205.14,175.88 220.7,175.88 221.97,177.15 225.78,177.15 226.41,176.52 236.57,176.52 239.43,179.37 v239.75,179.37 | v211.49,203.51 214.03,200.96 v214.03,200.33 | v217.21,182.55 214.35,179.69 206.41,179.69 205.46,180.64 B13.K2
SYNC_EN  (via drill 0.61)
  Top 0.254: v155.93,72.06 155.93,60.31 152.75,57.14 152.75,45.71 152.44,45.39 152.44,43.17 150.21,43.17 149.58,43.8 149.58,45.07 149.9,45.39 149.9,49.2 149.58,49.52 149.58,51.42 150.21,52.06 150.21,54.92 148.94,54.92 148.31,54.28 CD18.BH1 | v164.82,73.65 164.82,83.81 165.45,84.44 v165.45,84.76
  Route2 0.254: v165.45,84.76 165.45,86.98 179.74,101.27 179.74,101.91 185.14,107.3 185.14,107.94 v195.3,118.1 | v204.51,120.96 204.51,121.59 209.27,126.35 209.27,131.75 217.84,140.32 217.84,141.27 219.11,142.55 219.11,144.77 225.14,150.8 225.14,152.39 226.1,153.34 226.1,154.61 228,156.52 228.64,156.52 v239.43,167.31
  Route15 0.254: v239.43,167.31 237.21,169.53 233.4,169.53 232.13,170.8 232.13,172.39 230.54,173.98 B11.M2
  Bottom 0.254: v155.93,72.06 156.25,71.74 162.28,71.74 164.18,73.65 v164.82,73.65 | v195.3,118.1 196.57,119.37 202.92,119.37 v204.51,120.96
T3  (via drill 0.61)
  Top 0.254: v221.65,35.23 221.02,35.86 221.02,37.45 D12.N1 | v148.31,96.83 148.94,96.19 148.94,90.16 147.99,89.21 147.99,76.5 145.13,73.65 145.13,72.38 143.23,70.47 143.23,47.29 142.59,46.66 v142.59,39.99
  Bottom 0.254: v221.65,35.23 223.24,35.23 D12.P1 | v148.31,96.83 158.47,96.83 159.74,98.1 C17.S1 | v142.59,39.99 143.23,39.36 152.75,39.36 155.93,36.18 215.62,36.18 217.21,37.77 220.06,37.77 D12.N1
T_00\  (via drill 0.61)
  Top 0.254: v62.27,205.41 62.27,221.6 A24.V2 | v87.03,186.36 88.62,184.77 88.62,159.37 88.94,159.05 88.94,156.83 87.35,155.24 B22.V2
  Bottom 0.254: B23.V2 75.28,152.07 76.24,151.12 85.76,151.12 86.71,152.07 B22.V2 | v62.27,205.41 64.81,202.87 66.71,202.87 71.47,198.11 75.28,198.11 v87.03,186.36
T_01\  (via drill 0.61)
  Top 0.254: v72.74,245.73 76.24,242.24 v76.24,234.3 | v89.57,228.27 89.25,227.95 89.25,222.24 88.3,221.29 88.3,209.22 85.44,206.36 85.44,192.08 79.73,186.36 79.73,176.83 78.14,175.25 B23.M2
  Bottom 0.254: v72.74,245.73 66.71,245.73 65.76,244.78 A24.M2 | v76.24,234.3 76.87,233.67 81.95,233.67 83.54,232.08 A23.S1 84.81,231.45 86.4,231.45 v89.57,228.27
T_02\  (via drill 0.61)
  Top 0.254: v60.68,255.58 60.68,247 61,246.68 61,242.56 61.63,241.92 A24.N2 | v66.71,173.02 66.39,173.34 66.39,198.11 68.93,200.65 68.93,201.92 73.38,206.36 73.38,219.7 69.57,223.51 69.57,229.54 63.85,235.26 63.85,240.65 v64.17,240.97
  Bottom 0.254: v60.68,255.58 61,255.26 75.6,255.26 77.19,256.85 A23.H2 | v66.71,173.02 68.62,173.02 69.25,172.39 73.38,172.39 74.01,171.76 B23.N2 | v64.17,240.97 62.58,240.97 A24.N2
T_03\  (via drill 0.61)
  Top 0.254: A24.P2 65.44,238.75 66.39,239.7 66.39,242.56 74.33,250.49 74.33,253.35 A23.J2 | v92.11,251.13 92.11,244.14 91.79,243.83 91.79,220.33 88.94,217.48 88.94,202.87 86.08,200.01 86.08,191.44 82.9,188.27 82.9,187.31 82.27,186.68 82.27,177.15 79.09,173.98 79.09,169.85 78.14,168.9 B23.P2 | v84.49,252.4 82.59,252.4 82.59,254.3 v80.36,256.53
  Bottom 0.254: v92.11,251.13 90.84,252.4 v84.49,252.4 | v80.36,256.53 78.14,254.3 75.28,254.3 A23.J2
T_04\  (via drill 0.61)
  Top 0.254: 72.74,236.84 74.33,238.43 74.33,240.65 A23.N2 | 72.74,236.84 v71.16,235.26 | 72.74,236.84 72.74,228.59 73.38,227.95 73.38,221.6 74.65,220.33 74.65,205.73 73.06,204.14 73.06,202.24 72.74,201.92 72.74,167.31 74.33,165.72 B23.R2
  Bottom 0.254: v71.16,235.26 69.57,233.67 63.54,233.67 62.58,234.62 A24.R2
T_05\  (via drill 0.61)
  Top 0.254: 76.55,233.35 77.51,234.3 77.51,237.48 A23.P2 | 76.55,233.35 v73.7,230.49 | 76.55,233.35 76.55,203.19 75.92,202.55 75.92,180.01 76.24,179.69 76.24,163.82 77.51,162.55 B23.S2
  Bottom 0.254: v73.7,230.49 73.06,229.86 67.35,229.86 65.76,231.45 A24.S2
T_06\  (via drill 0.61)
  Top 0.254: v64.81,228.27 v67.35,225.73 | B23.T2 74.33,159.37 72.74,160.96 72.74,163.5 63.22,173.02 63.22,185.73 60.68,188.27 60.68,217.16 61,217.48 61,221.29 60.68,221.6 60.68,227 61.63,227.95 A24.T2
  Bottom 0.254: v64.81,228.27 62.58,228.27 A24.T2 | v67.35,225.73 68.93,224.14 76.24,224.14 77.19,225.09 A23.U2
T_07\  (via drill 0.61)
  Top 0.254: v72.43,221.92 72.43,221.6 74.01,220.02 74.01,206.05 69.57,201.6 69.57,168.26 75.92,161.91 75.92,157.79 77.51,156.2 B23.U2
  Bottom 0.254: 72.43,223.51 73.06,223.51 74.01,222.55 A23.V2 | 72.43,223.51 67.35,223.51 65.76,225.09 A24.U2 | v72.43,221.92 72.43,223.51
T_FWD\  (via drill 0.61)
  Top 0.254: v88.62,249.86 88.62,227 86.08,224.46 86.08,221.29 82.9,218.11 82.9,206.05 82.27,205.41 82.27,201.6 79.73,199.06 79.73,189.54 78.14,187.95 B23.H2 | v66.39,252.4 66.39,261.93 65.44,262.88 A24.E2
  Bottom 0.254: v88.62,249.86 87.98,250.49 84.81,250.49 A23.K1 83.54,251.13 82.59,252.08 66.71,252.08 v66.39,252.4
T_GO\  (via drill 0.61)
  Top 0.254: v63.54,198.43 63.22,198.74 63.22,264.15 v63.85,264.78 64.81,265.74 64.81,269.23 A24.C2
  Bottom 0.254: v63.54,198.43 68.62,198.43 69.57,197.47 73.7,197.47 74.01,197.15 B23.D2 | v63.85,264.78 78.78,264.78 80.36,266.37 A23.D1
T_PWR_CLR\  (via drill 0.61)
